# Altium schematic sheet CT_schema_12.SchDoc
size 145 x 119 mm
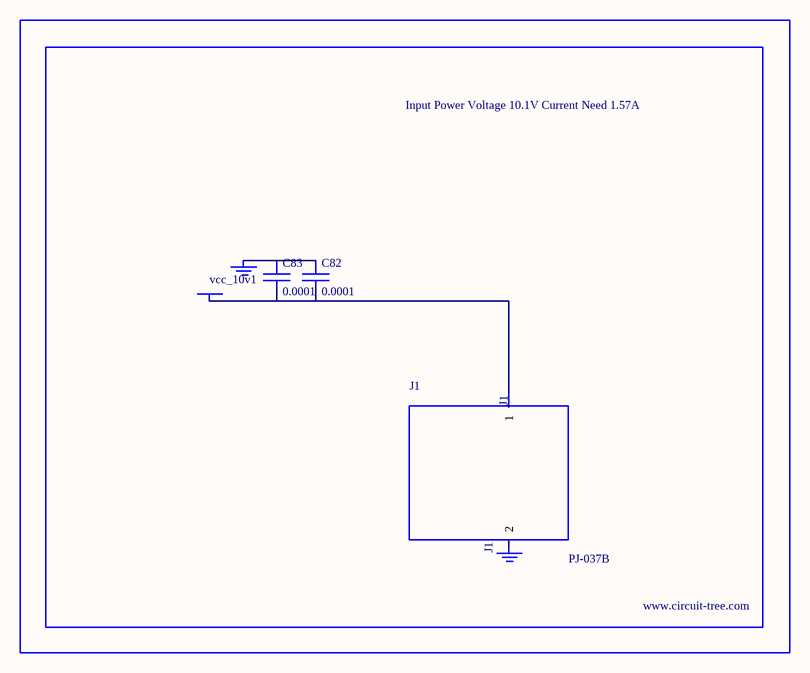
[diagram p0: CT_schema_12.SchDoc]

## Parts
BORDER11  (no value)
C82  0.0001  [EXV-9H]
C83  0.0001  [EXV-9H]
GND_INSTANCE_11_0  (no value)
GND_INSTANCE_11_1  (no value)
J1  PJ-037B  [PJ-037B_PACKAGE]
POWER_INSTANCE_11_0  vcc_10v1

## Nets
NetC82_1: C82.1 C83.1 GND_INSTANCE_11_0.0(GND)
NetC82_2: C82.2 C83.2 J1.1 POWER_INSTANCE_11_0.0(PWR)

Not connected (* = marked no-connect by the designer): GND_INSTANCE_11_1 0(GND); J1 2

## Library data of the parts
BORDER11 = BORDER_PAGE11
C82 C83 = EDK107M035A9HAA
GND_INSTANCE_11_0 GND_INSTANCE_11_1 = GND
POWER_INSTANCE_11_0 = PWR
